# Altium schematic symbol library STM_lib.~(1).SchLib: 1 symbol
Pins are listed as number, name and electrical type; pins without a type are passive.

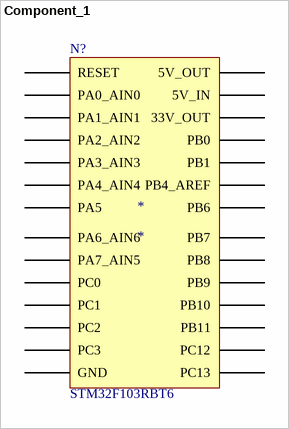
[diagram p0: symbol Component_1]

## Component_1
designator *
pins: 1 PB4_AREF, 2 PA0_AIN0, 3 PA1_AIN1, 4 PA2_AIN2, 5 PA3_AIN3, 6 PA4_AIN4, 7 PA7_AIN5, 8 PA6_AIN6, 9 PC0, 10 PC1, 11 PC2, 12 PC3, 13 PB7, 14 PB6, 15 5V_OUT, 16 5V_IN, 17 33V_OUT, 18 GND, 19 RESET, 20 PB1, 21 PB0, 22 PA5, 23 PB11, 24 PB10, 25 PB9, 26 PB8, 27 PC13, 28 PC12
